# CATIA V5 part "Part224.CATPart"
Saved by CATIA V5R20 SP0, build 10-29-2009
Part number: FA 168700-3
Revision: ANY
Definition: UNKNOWN
Nomenclature: FA 168700-3
Source: Unknown
Bounding box of the stored display mesh (mm): x -3 to 3, y 0 to 4.95, z -3.464 to 3.464
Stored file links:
  C:\Users\Utente\Desktop\IO LAVORO\3D X SITO CF\CUMSA\3D files FA\FA 200712-20\Part224.CATPart
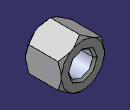
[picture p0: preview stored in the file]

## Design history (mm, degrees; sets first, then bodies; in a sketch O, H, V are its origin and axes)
Body1 "Cortar-Extruir3" (main body)
  Solid1: solid without history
